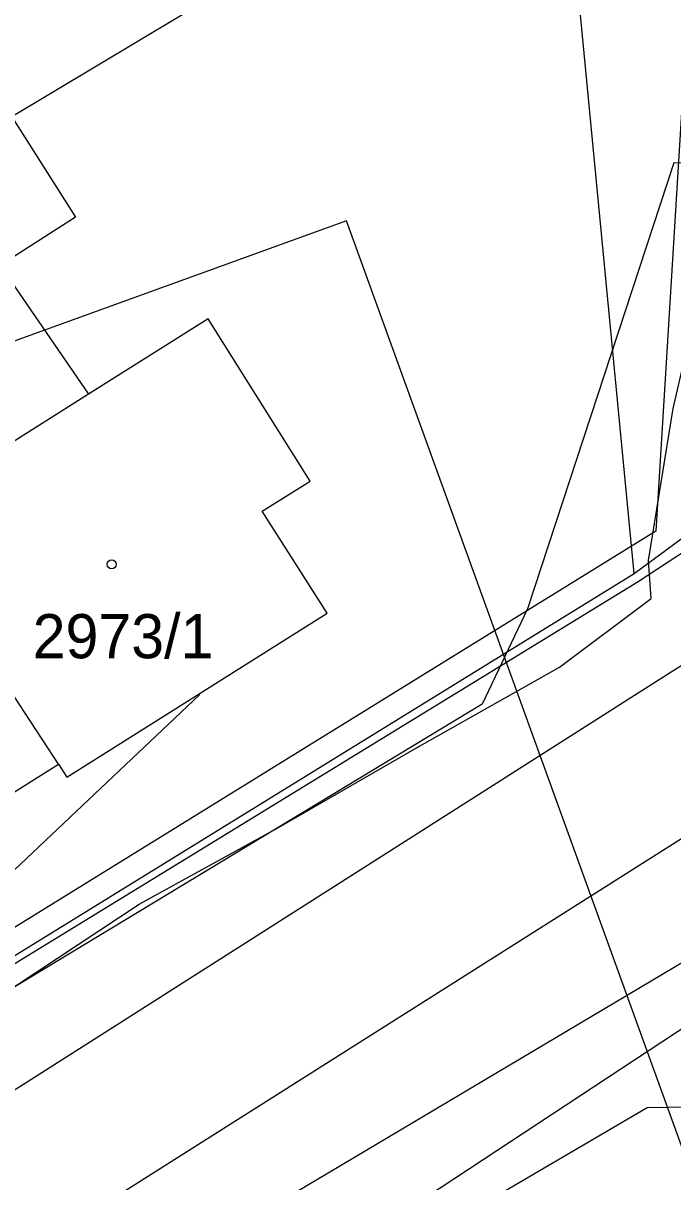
# Model space of a CAD drawing. Extents: x -620475 to -619963, y -1123010 to -1122510.
# Drawn here: x -620169.63 to -620144.64, y -1122926.57 to -1122881.99 of the extents above; entities that cross this region are included whole.
import ezdxf

# ---------------------------------------------------------------- set-up
doc = ezdxf.new("R2010")
doc.units = 0
for name, color, linetype in [('CD-T  SDK', 7, 'Continuous'), ('CETIN', 7, 'Continuous'), ('Hranice parcel', 7, 'Continuous'), ('Město Bystřice-osvětlení', 7, 'Continuous'), ('Parcelní čísla', 7, 'Continuous'), ('Rámečky', 7, 'Continuous'), ('Rámečky-tisk', 7, 'Continuous'), ('SSZT-DK SDK', 7, 'Continuous'), ('Vnitřní kresba', 7, 'Continuous'), ('Značky budov', 7, 'Continuous'), ('ČD-T OSS Ždár', 7, 'Continuous')]:
    doc.layers.add(name, color=color, linetype=linetype)

msp = doc.modelspace()

# ---------------------------------------------------------------- linework, layer by layer
at = {"layer": 'CD-T  SDK'}
msp.add_lwpolyline([(-620105.449, -1122868.581), (-620124.482, -1122881.511), (-620144.155, -1122882.921), (-620145.292, -1122901.532), (-620189.847, -1122929.066)], dxfattribs=at)
at = {"layer": 'CETIN'}
for points in [[(-620170.67, -1122919.52), (-620165.17, -1122915.89), (-620159.81, -1122912.93), (-620154.47, -1122909.86), (-620149, -1122906.77), (-620145.47, -1122904.13), (-620145.58, -1122902.66), (-620144.62, -1122896.82), (-620142.99, -1122889.79), (-620141.88, -1122887.3), (-620139.78, -1122884.72), (-620138.21, -1122884.47), (-620132.29, -1122883.5), (-620131.71, -1122883.41), (-620127.65, -1122882.75), (-620121.18, -1122878.38), (-620115.35, -1122873.32), (-620112.07, -1122871.4), (-620109.58, -1122869.93), (-620106.94, -1122868.3), (-620100.13, -1122864.1), (-620091.57, -1122858.83)], [(-620222.968, -1122953.743), (-620218.63, -1122950.99), (-620187.55, -1122931.18), (-620162.84, -1122907.83)], [(-620210.737, -1122964.442), (-620141.261, -1122918.677), (-620127.251, -1122919.476)]]:
    msp.add_lwpolyline(points, dxfattribs=at)
at = {"layer": 'Hranice parcel'}
for p, q in [((-620146.13, -1122903.17), (-620140.38, -1122898.92)), ((-620208, -1122941.31), (-620146.13, -1122903.17)), ((-620139.31, -1122915.18), (-620175.35, -1122936.6))]:
    msp.add_line(p, q, dxfattribs=at)
for points in [[(-620146.13, -1122903.17), (-620149.02, -1122872.99), (-620170.07, -1122885.6)], [(-620170.07, -1122885.6), (-620167.62, -1122889.46), (-620170.53, -1122891.31), (-620167.12, -1122896.26), (-620171.85, -1122899.25), (-620175.05, -1122894.19), (-620177.97, -1122896.04), (-620180.6, -1122891.9)], [(-620198.98, -1122917.79), (-620193.45, -1122926.35), (-620168.27, -1122910.5), (-620173.85, -1122901.99), (-620185.06, -1122909.04), (-620185.7, -1122908.03), (-620199.62, -1122916.78), (-620198.98, -1122917.79)]]:
    msp.add_lwpolyline(points, dxfattribs=at)
at = {"layer": 'Město Bystřice-osvětlení'}
msp.add_lwpolyline([(-620092.297, -1122836.326), (-620103.44, -1122876.118), (-620128.4, -1122892.9), (-620139.95, -1122899.534), (-620145.972, -1122903.483), (-620174.136, -1122920.728), (-620208.83, -1122942.099)], dxfattribs=at)
at = {"layer": 'Rámečky'}
msp.add_lwpolyline([(-620126.701, -1122973.8), (-620157.191, -1122889.6), (-620255.57, -1122925.224)], dxfattribs=at)
at = {"layer": 'Rámečky-tisk'}
msp.add_lwpolyline([(-620126.701, -1122973.8), (-620157.191, -1122889.6), (-620255.57, -1122925.224)], dxfattribs=at)
at = {"layer": 'SSZT-DK SDK'}
msp.add_lwpolyline([(-620098.563, -1122867.909), (-620125.234, -1122888.212), (-620144.595, -1122887.369), (-620150.227, -1122904.525), (-620151.977, -1122908.188), (-620181.024, -1122925.755)], dxfattribs=at)
at = {"layer": 'Vnitřní kresba'}
for p, q in [((-620162.51, -1122893.37), (-620167.12, -1122896.26)), ((-620158.59, -1122899.61), (-620162.51, -1122893.37)), ((-620160.44, -1122900.76), (-620158.59, -1122899.61)), ((-620157.94, -1122904.69), (-620160.44, -1122900.76)), ((-620140.04, -1122904.01), (-620144.7, -1122906.96)), ((-620167.95, -1122911), (-620157.94, -1122904.69)), ((-620144.7, -1122906.96), (-620220.97, -1122955.491)), ((-620168.27, -1122910.5), (-620167.95, -1122911)), ((-620141.9, -1122911.85), (-620216.732, -1122959.198))]:
    msp.add_line(p, q, dxfattribs=at)
at = {"layer": 'Značky budov'}
msp.add_circle((-620166.227, -1122902.809), 0.175, dxfattribs=at)
at = {"layer": 'ČD-T OSS Ždár'}
msp.add_lwpolyline([(-620090.831, -1122896.183), (-620117.323, -1122909.731), (-620123.829, -1122913.059), (-620127.58, -1122923.445), (-620145.628, -1122923.723), (-620198.095, -1122954.464)], dxfattribs=at)

# ---------------------------------------------------------------- texts
at = {"layer": 'Parcelní čísla'}
msp.add_text('2973/1', height=1.7, dxfattribs=at).set_placement((-620169.265, -1122906.426))

doc.saveas('drawing.dxf')
